(* Logix 5000 project; controller logix5561 vendor 1 type 14 code 54 rev 19.11; software revision 19.01 *)

TASK MainTask (continuous, watchdog 500 ms) : MainProgram

MODULES
   Local : vendor 1 type 14 code 54 (ICP 0, rev 19.11)
      eipscanner : 1756-ENBT (ICP 1, Ethernet 192.168.16.199, rev 6.1)
         A7NETH_2P : ETHERNET-MODULE (Ethernet 192.168.16.22, rev 1.1, Output RPI 10 ms)
END_MODULES

ADD_ON_INSTRUCTION A7NETH2P_Generic_Default_IO   (* revision 1.0 *)
// Simple interface for generic default IO mapping that uses Input Assembly Instance 150 and Output Assembly Instance 100.
VAR_IN_OUT
   I_Data : INT[2]; {required}   // Input data
   O_Data : INT[2]; {required}   // Output data
        [0]   // Output
END_VAR
VAR_INPUT
   RunStop : BOOL; {access Read Only, required}   // Run (0) or Stop (1)
   Forward : BOOL; {access Read Only, required}   // Run forward direction
   Reverse : BOOL; {required}   // Run reverse direction
   Reset : BOOL; {required}   // Reset the fault
   FrequencyCommand : INT; {access Read Only, required}   // Frequency command/reference
END_VAR
VAR_OUTPUT
   RunningStopped : BOOL; {access Read Only, visible}   // Running (1) or Stopped (0)
   RunningForward : BOOL; {visible}   // Running forward direction
   RunningReverse : BOOL; {visible}   // Running reverse direction
   UpToFrequency : BOOL; {access Read Only, visible}   // Up to frequency
   Alarm : BOOL; {access Read Only, visible}   // Alarm or Trip
   OutputFrequency : INT; {access Read Only, visible}   // Output/feedback frequency
END_VAR

ROUTINE Logic   (* ladder *)
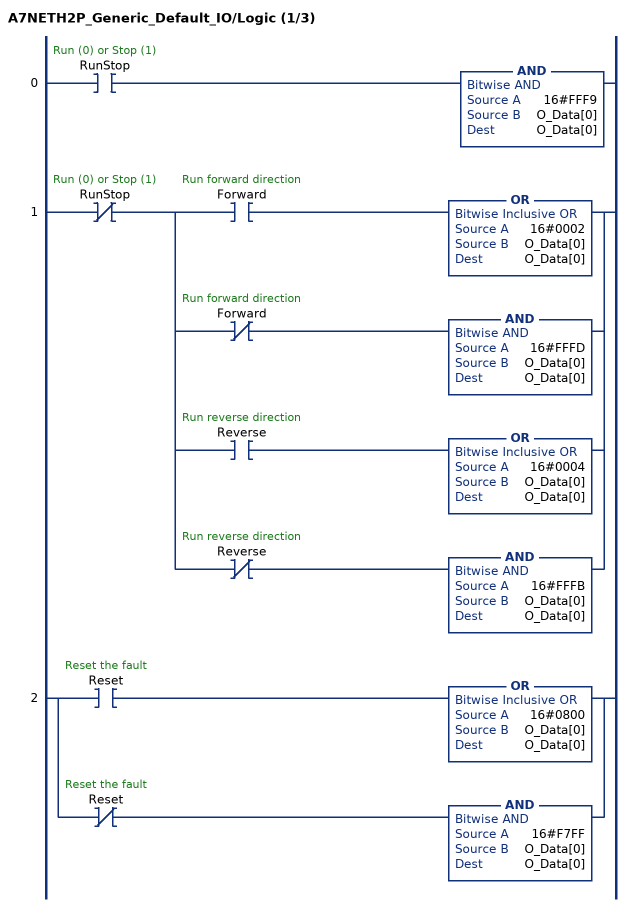
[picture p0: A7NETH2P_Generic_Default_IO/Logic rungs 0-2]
   0: XIC(RunStop)AND(16#FFF9,O_Data[0],O_Data[0]);
   1: XIO(RunStop)[XIC(Forward) OR(16#0002,O_Data[0],O_Data[0]) ,XIO(Forward) AND(16#FFFD,O_Data[0],O_Data[0]) ,XIC(Reverse) OR(16#0004,O_Data[0],O_Data[0]) ,XIO(Reverse) AND(16#FFFB,O_Data[0],O_Data[0]) ];
   2: [XIC(Reset) OR(16#0800,O_Data[0],O_Data[0]) ,XIO(Reset) AND(16#F7FF,O_Data[0],O_Data[0]) ];
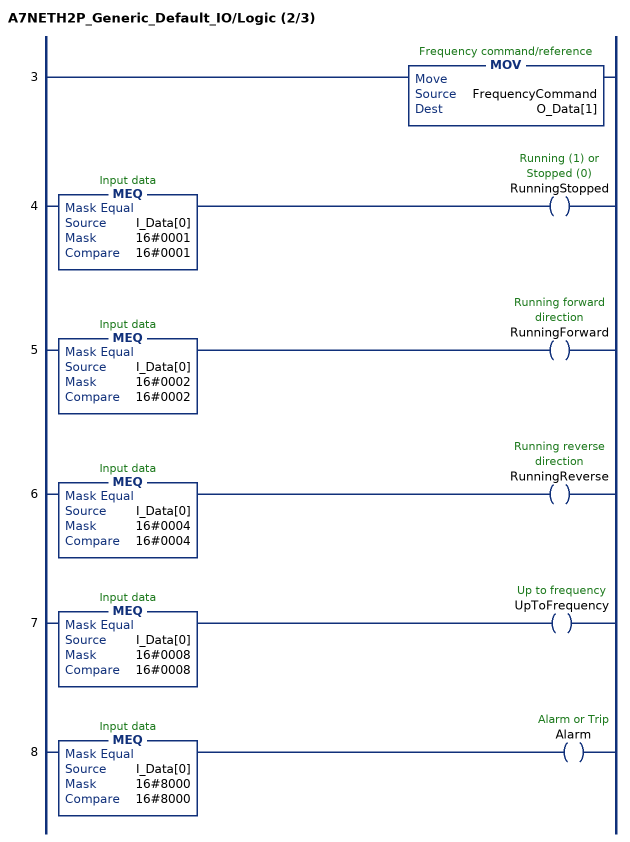
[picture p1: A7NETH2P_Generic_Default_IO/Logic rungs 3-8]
   3: MOV(FrequencyCommand,O_Data[1]);
   4: MEQ(I_Data[0],16#0001,16#0001)OTE(RunningStopped);
   5: MEQ(I_Data[0],16#0002,16#0002)OTE(RunningForward);
   6: MEQ(I_Data[0],16#0004,16#0004)OTE(RunningReverse);
   7: MEQ(I_Data[0],16#0008,16#0008)OTE(UpToFrequency);
   8: MEQ(I_Data[0],16#8000,16#8000)OTE(Alarm);
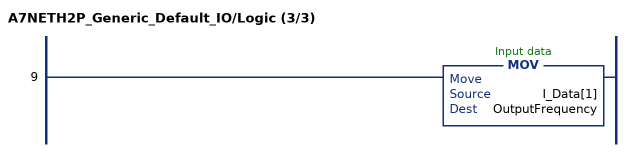
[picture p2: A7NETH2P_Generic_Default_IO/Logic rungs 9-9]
   9: MOV(I_Data[1],OutputFrequency);
END_ROUTINE
END_ADD_ON_INSTRUCTION

VAR_GLOBAL   (* controller tags *)
   freq_cmd : INT;   // Frequency command (hertz)
   fwd : BOOL;   // Forward direction
   generic_aoi : A7NETH2P_Generic_Default_IO;
   reset : BOOL;   // Reset alarm or fault
   rev : BOOL;   // Reverse direction
   run_stop : BOOL;   // 0 = Run, 1 = Stop
END_VAR

PROGRAM MainProgram   (* main routine MainRoutine *)

ROUTINE MainRoutine   (* ladder *)
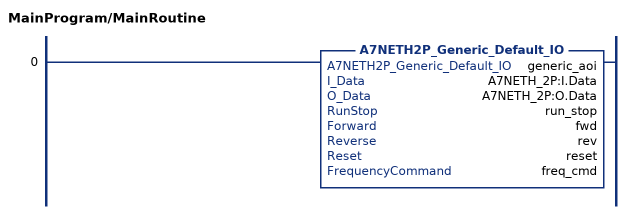
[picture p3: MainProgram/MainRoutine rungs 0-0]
   0: A7NETH2P_Generic_Default_IO(generic_aoi,A7NETH_2P:I.Data,A7NETH_2P:O.Data,run_stop,fwd,rev,reset,freq_cmd);
END_ROUTINE
END_PROGRAM
